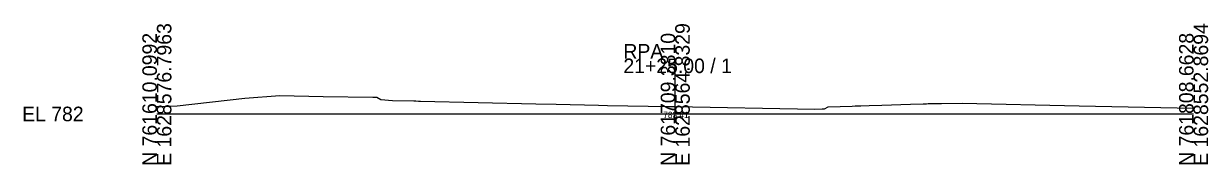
# Model space of a CAD drawing. Extents: x -26 to 203, y 990 to 7517.
# Drawn here: x -25.7 to 202.8, y 6490.3 to 6517.4 of the extents above; entities that cross this region are included whole.
import ezdxf

# ---------------------------------------------------------------- set-up
doc = ezdxf.new("R2010")
doc.units = 0
for name, color, linetype in [('Exist Cross Section Cell', 7, 'Continuous'), ('Exist XS Center Line Elevation Label', 7, 'Continuous'), ('Exist XS Ground Line', 7, 'Continuous')]:
    doc.layers.add(name, color=color, linetype=linetype)

msp = doc.modelspace()

# ---------------------------------------------------------------- linework, layer by layer
at = {"layer": 'Exist Cross Section Cell'}
for p, q in [((100, 6500), (100, 6510.67)), ((0, 6500), (100, 6500)), ((100, 6500), (200, 6500))]:
    msp.add_line(p, q, dxfattribs=at)
at = {"layer": 'Exist XS Ground Line'}
for p, q in [((3.92, 6501.58), (16.94, 6503.06)), ((16.94, 6503.06), (23.73, 6503.56)), ((23.73, 6503.56), (32.1, 6503.33)), ((32.1, 6503.33), (41.67, 6503.24)), ((41.67, 6503.24), (42.46, 6503.22)), ((42.46, 6503.22), (43.2, 6502.76)), ((43.2, 6502.76), (45.46, 6502.61)), ((45.46, 6502.61), (49.57, 6502.51)), ((49.57, 6502.51), (49.95, 6502.51)), ((49.95, 6502.51), (50.48, 6502.49)), ((50.48, 6502.49), (50.88, 6502.48)), ((50.88, 6502.48), (73.08, 6501.96)), ((73.08, 6501.96), (77.01, 6501.87)), ((77.01, 6501.87), (85.17, 6501.68)), ((139.87, 6501.71), (145.41, 6501.89)), ((145.41, 6501.89), (147.81, 6501.95)), ((147.81, 6501.95), (148.48, 6501.97)), ((148.48, 6501.97), (148.82, 6501.98)), ((148.82, 6501.98), (149.7, 6502)), ((149.7, 6502), (150.52, 6502.01)), ((150.52, 6502.01), (151.34, 6502.01)), ((151.34, 6502.01), (155.33, 6502.05)), ((155.33, 6502.05), (177.94, 6501.53)), ((0, 6501.42), (3.92, 6501.58)), ((85.17, 6501.68), (86.95, 6501.64)), ((86.95, 6501.64), (98.69, 6501.43)), ((98.69, 6501.43), (100, 6501.41)), ((100, 6501.41), (126.95, 6500.95)), ((126.95, 6500.95), (128.32, 6500.98)), ((128.32, 6500.98), (128.77, 6500.98)), ((128.77, 6500.98), (129.53, 6501.34)), ((129.53, 6501.34), (134.15, 6501.52)), ((134.15, 6501.52), (134.71, 6501.54)), ((134.71, 6501.54), (135.78, 6501.56)), ((135.78, 6501.56), (137.43, 6501.63)), ((137.43, 6501.63), (139.87, 6501.71)), ((177.94, 6501.53), (200, 6501.1))]:
    msp.add_line(p, q, dxfattribs=at)

# ---------------------------------------------------------------- texts
at = {"layer": 'Exist Cross Section Cell'}
for s, p in [('E 1628576.7963', (2.8, 6490)), ('E 1628564.8329', (102.8, 6490)), ('E 1628552.8694', (202.8, 6490)), ('N 761610.0992', (0, 6490)), ('N 761709.3810', (100, 6490)), ('N 761808.6628', (200, 6490))]:
    msp.add_text(s, height=2.8, rotation=90, dxfattribs=at).set_placement(p)
for s, p in [('RPA', (90, 6510.67)), ('21+25.00 / 1', (90, 6507.87)), ('EL 782', (-26, 6498.6))]:
    msp.add_text(s, height=2.8, dxfattribs=at).set_placement(p)
at = {"layer": 'Exist XS Center Line Elevation Label'}
msp.add_text('783.41', height=1.2, dxfattribs=at).set_placement((97.69, 6499.21))

doc.saveas('drawing.dxf')
